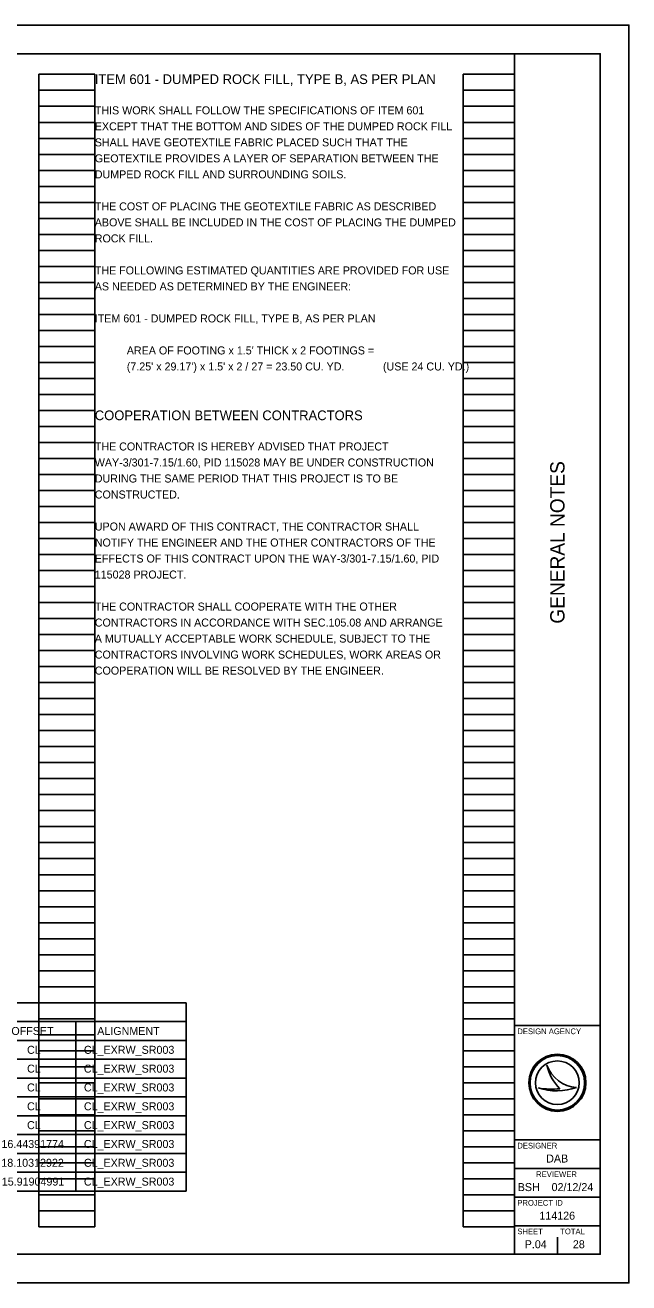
# Model space of a CAD drawing. Extents: x -7.6 to 34, y 0 to 22.
# Drawn here: x 23.44 to 34, y 0 to 22 of the extents above; entities that cross this region are included whole.
import ezdxf

# ---------------------------------------------------------------- set-up
doc = ezdxf.new("R2010")
doc.units = 0
for name, color, linetype in [('SH_Border', 7, 'Continuous'), ('SH_Cut_Line', 7, 'Continuous'), ('SH_Data', 7, 'Continuous'), ('SH_Text', 7, 'Continuous')]:
    doc.layers.add(name, color=color, linetype=linetype)

msp = doc.modelspace()

# ---------------------------------------------------------------- linework, layer by layer
at = {"layer": 'SH_Border'}
for p, q in [((32, 0.5), (32, 21.5)), ((32, 4.5), (33.5, 4.5)), ((32, 2.5), (33.5, 2.5)), ((32, 2), (33.5, 2)), ((32, 1.5), (33.5, 1.5)), ((32, 1), (33.5, 1))]:
    msp.add_line(p, q, dxfattribs=at)
msp.add_lwpolyline([(1.5, 21.5), (33.5, 21.5), (33.5, 0.5), (1.5, 0.5)], close=True, dxfattribs=at)
at = {"layer": 'SH_Cut_Line'}
msp.add_lwpolyline([(0, 0), (34, 0), (34, 22), (0, 22)], close=True, dxfattribs=at)
at = {"layer": 'SH_Data'}
for p, q in [((23.68, 0.98), (23.68, 21.14)), ((23.68, 21.14), (24.66, 21.14)), ((24.66, 0.98), (24.66, 21.14)), ((31.1, 0.98), (31.1, 21.14)), ((31.1, 21.14), (32, 21.14)), ((32, 0.98), (32, 21.14)), ((23.68, 20.86), (24.66, 20.86)), ((31.1, 20.86), (32, 20.86)), ((23.68, 20.58), (24.66, 20.58)), ((31.1, 20.58), (32, 20.58)), ((23.68, 20.3), (24.66, 20.3)), ((31.1, 20.3), (32, 20.3)), ((23.68, 20.02), (24.66, 20.02)), ((31.1, 20.02), (32, 20.02)), ((23.68, 19.74), (24.66, 19.74)), ((31.1, 19.74), (32, 19.74)), ((23.68, 19.46), (24.66, 19.46)), ((31.1, 19.46), (32, 19.46)), ((23.68, 19.18), (24.66, 19.18)), ((31.1, 19.18), (32, 19.18)), ((23.68, 18.9), (24.66, 18.9)), ((31.1, 18.9), (32, 18.9)), ((23.68, 18.62), (24.66, 18.62)), ((31.1, 18.62), (32, 18.62)), ((23.68, 18.34), (24.66, 18.34)), ((31.1, 18.34), (32, 18.34)), ((23.68, 18.06), (24.66, 18.06)), ((31.1, 18.06), (32, 18.06)), ((23.68, 17.78), (24.66, 17.78)), ((31.1, 17.78), (32, 17.78)), ((23.68, 17.5), (24.66, 17.5)), ((31.1, 17.5), (32, 17.5)), ((23.68, 17.22), (24.66, 17.22)), ((31.1, 17.22), (32, 17.22)), ((23.68, 16.94), (24.66, 16.94)), ((31.1, 16.94), (32, 16.94)), ((23.68, 16.66), (24.66, 16.66)), ((31.1, 16.66), (32, 16.66)), ((23.68, 16.38), (24.66, 16.38)), ((31.1, 16.38), (32, 16.38)), ((23.68, 16.1), (24.66, 16.1)), ((31.1, 16.1), (32, 16.1)), ((23.68, 15.82), (24.66, 15.82)), ((31.1, 15.82), (32, 15.82)), ((23.68, 15.54), (24.66, 15.54)), ((31.1, 15.54), (32, 15.54)), ((23.68, 15.26), (24.66, 15.26)), ((31.1, 15.26), (32, 15.26)), ((23.68, 14.98), (24.66, 14.98)), ((31.1, 14.98), (32, 14.98)), ((23.68, 14.7), (24.66, 14.7)), ((31.1, 14.7), (32, 14.7)), ((23.68, 14.42), (24.66, 14.42)), ((31.1, 14.42), (32, 14.42)), ((23.68, 14.14), (24.66, 14.14)), ((31.1, 14.14), (32, 14.14)), ((23.68, 13.86), (24.66, 13.86)), ((31.1, 13.86), (32, 13.86)), ((23.68, 13.58), (24.66, 13.58)), ((31.1, 13.58), (32, 13.58)), ((23.68, 13.3), (24.66, 13.3)), ((31.1, 13.3), (32, 13.3)), ((23.68, 13.02), (24.66, 13.02)), ((31.1, 13.02), (32, 13.02)), ((23.68, 12.74), (24.66, 12.74)), ((31.1, 12.74), (32, 12.74)), ((23.68, 12.46), (24.66, 12.46)), ((31.1, 12.46), (32, 12.46)), ((23.68, 12.18), (24.66, 12.18)), ((31.1, 12.18), (32, 12.18)), ((23.68, 11.9), (24.66, 11.9)), ((31.1, 11.9), (32, 11.9)), ((23.68, 11.62), (24.66, 11.62)), ((31.1, 11.62), (32, 11.62)), ((23.68, 11.34), (24.66, 11.34)), ((31.1, 11.34), (32, 11.34)), ((23.68, 11.06), (24.66, 11.06)), ((31.1, 11.06), (32, 11.06)), ((23.68, 10.78), (24.66, 10.78)), ((31.1, 10.78), (32, 10.78)), ((23.68, 10.5), (24.66, 10.5)), ((31.1, 10.5), (32, 10.5)), ((23.68, 10.22), (24.66, 10.22)), ((31.1, 10.22), (32, 10.22)), ((23.68, 9.94), (24.66, 9.94)), ((31.1, 9.94), (32, 9.94)), ((23.68, 9.66), (24.66, 9.66)), ((31.1, 9.66), (32, 9.66)), ((23.68, 9.38), (24.66, 9.38)), ((31.1, 9.38), (32, 9.38)), ((23.68, 9.1), (24.66, 9.1)), ((31.1, 9.1), (32, 9.1)), ((23.68, 8.82), (24.66, 8.82)), ((31.1, 8.82), (32, 8.82)), ((23.68, 8.54), (24.66, 8.54)), ((31.1, 8.54), (32, 8.54)), ((23.68, 8.26), (24.66, 8.26)), ((31.1, 8.26), (32, 8.26)), ((23.68, 7.98), (24.66, 7.98)), ((31.1, 7.98), (32, 7.98)), ((23.68, 7.7), (24.66, 7.7)), ((31.1, 7.7), (32, 7.7)), ((23.68, 7.42), (24.66, 7.42)), ((31.1, 7.42), (32, 7.42)), ((23.68, 7.14), (24.66, 7.14)), ((31.1, 7.14), (32, 7.14)), ((23.68, 6.86), (24.66, 6.86)), ((31.1, 6.86), (32, 6.86)), ((23.68, 6.58), (24.66, 6.58)), ((31.1, 6.58), (32, 6.58)), ((23.68, 6.3), (24.66, 6.3)), ((31.1, 6.3), (32, 6.3)), ((23.68, 6.02), (24.66, 6.02)), ((31.1, 6.02), (32, 6.02)), ((23.68, 5.74), (24.66, 5.74)), ((31.1, 5.74), (32, 5.74)), ((23.68, 5.46), (24.66, 5.46)), ((31.1, 5.46), (32, 5.46)), ((23.68, 5.18), (24.66, 5.18)), ((31.1, 5.18), (32, 5.18)), ((23.68, 4.9), (24.66, 4.9)), ((31.1, 4.9), (32, 4.9)), ((23.68, 4.62), (24.66, 4.62)), ((31.1, 4.62), (32, 4.62)), ((23.68, 4.34), (24.66, 4.34)), ((31.1, 4.34), (32, 4.34)), ((23.68, 4.06), (24.66, 4.06)), ((31.1, 4.06), (32, 4.06)), ((23.68, 3.78), (24.66, 3.78)), ((31.1, 3.78), (32, 3.78)), ((32.567, 3.81), (32.567, 3.81)), ((23.68, 3.5), (24.66, 3.5)), ((31.1, 3.5), (32, 3.5)), ((32.417, 3.41), (32.417, 3.41)), ((32.75, 3.5), (32.75, 3.5)), ((33.087, 3.419), (33.087, 3.419)), ((23.68, 3.22), (24.66, 3.22)), ((31.1, 3.22), (32, 3.22)), ((23.68, 2.94), (24.66, 2.94)), ((31.1, 2.94), (32, 2.94)), ((23.68, 2.66), (24.66, 2.66)), ((31.1, 2.66), (32, 2.66)), ((23.68, 2.38), (24.66, 2.38)), ((31.1, 2.38), (32, 2.38)), ((23.68, 2.1), (24.66, 2.1)), ((31.1, 2.1), (32, 2.1)), ((23.68, 1.82), (24.66, 1.82)), ((31.1, 1.82), (32, 1.82)), ((23.68, 1.54), (24.66, 1.54)), ((31.1, 1.54), (32, 1.54)), ((23.68, 1.26), (24.66, 1.26)), ((31.1, 1.26), (32, 1.26)), ((23.68, 0.98), (24.66, 0.98)), ((31.1, 0.98), (32, 0.98)), ((32.375, 0.675), (32.375, 0.675)), ((32.75, 0.5), (32.75, 0.8))]:
    msp.add_line(p, q, dxfattribs=at)
for radius in [0.5, 0.477, 0.477, 0.382]:
    msp.add_circle((32.75, 3.5), radius, dxfattribs=at)
for centre, radius, start, end in [((33.116, 3.998), 0.58, 198.9257, 198.9319), ((33.347, 3.97), 0.796, 191.6379, 191.6421), ((33.116, 3.998), 0.58, 198.9319, 267.1657), ((33.347, 3.97), 0.796, 191.6421, 226.0947), ((32.739, 4.37), 1.013, 251.4576, 290.0832), ((32.648, 4.654), 1.266, 259.4964, 259.4995), ((32.739, 4.37), 1.013, 251.4527, 251.4576), ((32.648, 4.654), 1.266, 259.4995, 276.6672)]:
    msp.add_arc(centre, radius, start, end, dxfattribs=at)
at = {"layer": 'SH_Text'}
for p, q in [((9.82, 4.9), (26.258, 4.9)), ((26.258, 4.9), (26.258, 1.606)), ((9.82, 4.571), (26.258, 4.571)), ((24.331, 4.571), (24.331, 1.606)), ((9.82, 4.241), (26.258, 4.241)), ((9.82, 3.912), (26.258, 3.912)), ((9.82, 3.582), (26.258, 3.582)), ((9.82, 3.253), (26.258, 3.253)), ((9.82, 2.924), (26.258, 2.924)), ((9.82, 2.594), (26.258, 2.594)), ((9.82, 2.265), (26.258, 2.265)), ((9.82, 1.935), (26.258, 1.935)), ((9.82, 1.606), (26.258, 1.606))]:
    msp.add_line(p, q, dxfattribs=at)

# ---------------------------------------------------------------- texts
at = {"layer": 'SH_Data'}
msp.add_text('GENERAL NOTES', height=0.25, rotation=90, dxfattribs=at).set_placement((32.875, 11.531))
for s, height, p in [('DESIGN AGENCY', 0.1, (32.05, 4.35)), ('DESIGNER', 0.1, (32.05, 2.35)), ('DAB', 0.14, (32.554, 2.105)), ('REVIEWER', 0.1, (32.378, 1.85)), ('BSH', 0.14, (32.057, 1.605)), ('02/12/24', 0.14, (32.649, 1.605)), ('PROJECT ID', 0.1, (32.05, 1.35)), ('114126', 0.14, (32.435, 1.105)), ('SHEET', 0.1, (32.05, 0.85)), ('TOTAL', 0.1, (32.8, 0.85)), ('P.04', 0.14, (32.179, 0.605)), ('28', 0.14, (33.021, 0.605))]:
    msp.add_text(s, height=height, dxfattribs=at).set_placement(p)
at = {"layer": 'SH_Text'}
for s, height, p in [('ITEM 601 - DUMPED ROCK FILL, TYPE B, AS PER PLAN', 0.17, (24.66, 20.97)), ('THIS WORK SHALL FOLLOW THE SPECIFICATIONS OF ITEM 601 ', 0.14, (24.66, 20.44)), ('EXCEPT THAT THE BOTTOM AND SIDES OF THE DUMPED ROCK FILL ', 0.14, (24.66, 20.16)), ('SHALL HAVE GEOTEXTILE FABRIC PLACED SUCH THAT THE ', 0.14, (24.66, 19.88)), ('GEOTEXTILE PROVIDES A LAYER OF SEPARATION BETWEEN THE ', 0.14, (24.66, 19.6)), ('DUMPED ROCK FILL AND SURROUNDING SOILS.', 0.14, (24.66, 19.32)), ('THE COST OF PLACING THE GEOTEXTILE FABRIC AS DESCRIBED ', 0.14, (24.66, 18.76)), ('ABOVE SHALL BE INCLUDED IN THE COST OF PLACING THE DUMPED ', 0.14, (24.66, 18.48)), ('ROCK FILL.', 0.14, (24.66, 18.2)), ('THE FOLLOWING ESTIMATED QUANTITIES ARE PROVIDED FOR USE ', 0.14, (24.66, 17.64)), ('AS NEEDED AS DETERMINED BY THE ENGINEER:', 0.14, (24.66, 17.36)), ('ITEM 601 - DUMPED ROCK FILL, TYPE B, AS PER PLAN', 0.14, (24.66, 16.8)), ("AREA OF FOOTING x 1.5' THICK x 2 FOOTINGS =", 0.14, (25.22, 16.24)), ("(7.25' x 29.17') x 1.5' x 2 / 27 = 23.50 CU. YD.", 0.14, (25.22, 15.96)), ('(USE 24 CU. YD.)', 0.14, (29.7, 15.96)), ('COOPERATION BETWEEN CONTRACTORS', 0.17, (24.66, 15.09)), ('THE CONTRACTOR IS HEREBY ADVISED THAT PROJECT', 0.14, (24.66, 14.56)), ('WAY-3/301-7.15/1.60, PID 115028 MAY BE UNDER CONSTRUCTION ', 0.14, (24.66, 14.28)), ('DURING THE SAME PERIOD THAT THIS PROJECT IS TO BE ', 0.14, (24.66, 14)), ('CONSTRUCTED. ', 0.14, (24.66, 13.72)), ('UPON AWARD OF THIS CONTRACT, THE CONTRACTOR SHALL ', 0.14, (24.66, 13.16)), ('NOTIFY THE ENGINEER AND THE OTHER CONTRACTORS OF THE ', 0.14, (24.66, 12.88)), ('EFFECTS OF THIS CONTRACT UPON THE WAY-3/301-7.15/1.60, PID ', 0.14, (24.66, 12.6)), ('115028 PROJECT. ', 0.14, (24.66, 12.32)), ('THE CONTRACTOR SHALL COOPERATE WITH THE OTHER ', 0.14, (24.66, 11.76)), ('CONTRACTORS IN ACCORDANCE WITH SEC.105.08 AND ARRANGE ', 0.14, (24.66, 11.48)), ('A MUTUALLY ACCEPTABLE WORK SCHEDULE, SUBJECT TO THE ', 0.14, (24.66, 11.2)), ('CONTRACTORS INVOLVING WORK SCHEDULES, WORK AREAS OR ', 0.14, (24.66, 10.92)), ('COOPERATION WILL BE RESOLVED BY THE ENGINEER.', 0.14, (24.66, 10.64)), ('OFFSET', 0.14, (23.202, 4.336)), ('ALIGNMENT', 0.14, (24.703, 4.336)), ('CL', 0.14, (23.476, 4.006)), ('CL_EXRW_SR003', 0.14, (24.47, 4.006)), ('CL', 0.14, (23.476, 3.677)), ('CL_EXRW_SR003', 0.14, (24.47, 3.677)), ('CL', 0.14, (23.476, 3.348)), ('CL_EXRW_SR003', 0.14, (24.47, 3.348)), ('CL', 0.14, (23.476, 3.018)), ('CL_EXRW_SR003', 0.14, (24.47, 3.018)), ('CL', 0.14, (23.476, 2.689)), ('CL_EXRW_SR003', 0.14, (24.47, 2.689)), ('16.44391774', 0.14, (23.028, 2.359)), ('CL_EXRW_SR003', 0.14, (24.47, 2.359)), ('18.10312922', 0.14, (23.026, 2.03)), ('CL_EXRW_SR003', 0.14, (24.47, 2.03)), ('15.91904991', 0.14, (23.034, 1.701)), ('CL_EXRW_SR003', 0.14, (24.47, 1.701))]:
    msp.add_text(s, height=height, dxfattribs=at).set_placement(p)

doc.saveas('drawing.dxf')
